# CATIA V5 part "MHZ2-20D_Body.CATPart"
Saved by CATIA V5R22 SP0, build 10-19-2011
Part number: MHZ2-20D_Body
Property "ParasolidId": 3
Property "PSOL_INSTNR": 1
Bounding box of the stored display mesh (mm): x -25 to 25, y -13.8 to 13.8, z 0 to 62.3
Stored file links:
  U:\S9A\PER\CAO\Assemblage\Cadre\Chariot_Y\Prehenseur\MHZ2-20D_Body.CATPart
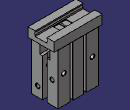
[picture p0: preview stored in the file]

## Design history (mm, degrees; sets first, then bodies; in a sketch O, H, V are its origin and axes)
Body1 "MHZ2-20D_Body" (main body)
  Solid1: solid without history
